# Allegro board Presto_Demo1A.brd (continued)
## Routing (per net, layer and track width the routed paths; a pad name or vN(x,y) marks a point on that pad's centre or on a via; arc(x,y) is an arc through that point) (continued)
A14: length 29.6
  TOP w0.2: U8.38 24.46,118.09 24.31,118.24 v2(24.3,118.24)
  INNER1 w0.2: v2(24.3,118.24) 23.16,117.11 23.05,117.11 22.7,116.75 22.7,115.44 20.4,113.15 20.4,111.14 18.67,109.4 14.75,109.4 14.45,109.1 14.45,100.2 14.08,99.83 J6.B10
A15: length 33
  TOP w0.2: U8.37 26.89,117.59 v2(26.9,117.6)
  INNER1 w0.2: J6.B9 10.88,97.3 13.75,97.3 14.85,98.4 14.85,108.8 15.05,109 18.83,109 20.8,110.97 20.8,112.98 25.42,117.6 v2(26.9,117.6)
A16: length 24.1
  TOP w0.2: J6.B24 12.24,135.39 12.9,136.05 12.9,137.88 16.52,141.51 20.71,141.51 21.95,140.26 21.95,139.94 21.95,139.93 21.95,138 23.55,136.4 23.55,134.86 23.54,134.85 23.54,134.35 24.03,133.86 24.83,133.86 24.84,133.86 U6.36
A17: length 25.4
  TOP w0.2: J6.B23 11.77,133.75 11.77,134.22 13.3,135.75 13.3,137.72 16.69,141.11 20.54,141.11 21.55,140.1 21.55,137.84 23.14,136.24 23.14,134.18 23.92,133.41 24.55,133.41 24.6,133.36 U6.35
A18: length 93.9
  TOP w0.2: U6.33 24.74,132.36 v2(24.3,132.8) 23.8,132.8 22.74,133.86 22.74,136.08 21.15,137.67 21.15,139.93 20.38,140.71 16.85,140.71 13.7,137.55 13.7,131.62 12.39,130.31 J6.B22 ; U7.6 17.78,81.53 18.1,81.85 v2(18.1,81.9)
  INNER2 w0.2: v2(18.1,81.9) 18.15,81.84 20.41,81.84 29.2,90.63 29.2,109.45 21.6,117.04 21.6,119.78 22.3,120.48 22.3,125.65 23.5,126.85 24.97,126.85 26.14,128.03 26.14,130.96 v2(24.3,132.8)
A19: length 94.3
  TOP w0.2: J6.B21 13.27,127.77 14.1,128.6 14.1,137.39 17.02,140.31 20.21,140.31 20.75,139.77 20.75,137.51 22.34,135.91 22.34,133.69 24.13,131.9 v2(24.3,131.9) 25.6,131.9 U6.32 ; v2(18,82.8) U7.5
  INNER2 w0.2: v2(24.3,131.9) 25.74,130.46 25.74,128.19 24.8,127.25 23.34,127.25 21.9,125.81 21.9,120.65 21.2,119.95 21.2,117.21 21.2,117.21 21.2,116.88 28.8,109.28 28.8,90.8 21.15,83.15 19.2,83.15 18.84,82.8 v2(18,82.8)
A20: length 80.6
  TOP w0.2: v2(24.05,130.95) 24.05,130.95 24.15,130.85 25.64,130.85 U6.30 ; U7.4 16.67,84.1 v2(18.74,84.1)
  INNER1 w0.2: J6.B20 10.87,126.57 10.02,127.42 10.02,128.12 11.54,129.65 14.6,129.65 16.1,131.15 17.5,131.15 18.15,130.5 23.59,130.5 v2(24.05,130.95)
  INNER2 w0.2: v2(24.05,130.95) 23.49,130.4 23.49,129.85 23.8,129.54 23.8,128.85 21.1,126.14 21.1,120.98 20.4,120.28 20.4,117.54 20.4,117.54 20.4,117.21 20.4,116.55 20.4,116.55 20.4,114.36 28,106.77 28,91.13 24.02,87.16 20.15,87.16 18.74,85.75 v2(18.74,84.1)
A21: length 79.9
  TOP w0.2: U6.29 25.64,130.35 24.35,130.35 v2(24.1,130.1) ; v2(20.4,86.55) 19.25,85.4 16.7,85.4 16.64,85.34
  INNER1 w0.2: J6.B19 11.77,123.59 11.77,127.11 12.26,127.61 13.1,127.61 14.75,129.25 14.77,129.25 16.22,130.7 17.38,130.7 17.98,130.1 v2(24.1,130.1)
  INNER2 w0.2: v2(24.1,130.1) 24.15,130.1 25.02,129.23 25.02,128.11 24.56,127.65 23.17,127.65 21.5,125.98 21.5,120.81 20.8,120.12 20.8,117.38 20.8,116.71 20.8,116.71 20.8,114.53 28.4,106.93 28.4,90.96 23.98,86.55 v2(20.4,86.55)
A22: length 83.3
  TOP w0.2: v2(23.2,129.1) 23.46,129.36 U6.27 ; U7.2 14.51,86.61 v2(14.5,86.6)
  INNER1 w0.2: v2(23.2,129.1) 22.6,129.7 18.2,129.7 17.9,129.4 17.01,129.4 17,129.41 16.5,129.41 16.14,129.05 16.14,129.05 15.6,128.5 14.73,128.5 13.64,127.42 13.64,126.56 13.24,126.16 13.24,125.28 13.25,125.28 13.25,124.78 14,124.03 14,120.82 13.33,120.15 J6.B18
  INNER2 w0.2: v2(23.2,129.1) 20.7,126.6 20.7,121.14 20,120.45 20,117.71 20,117.38 20,117.38 20,116.38 20,116.38 20,114.19 27.6,106.6 27.6,91.3 23.86,87.56 19.96,87.56 19,86.6 v2(14.5,86.6)
A23: length 27.2
  TOP w0.2: v2(26.95,128.9) 25.69,128.9 U6.26
  INNER1 w0.2: J6.B17 10.87,118.32 12.02,119.48 13.22,119.48 14.4,120.65 14.4,124.2 13.65,124.95 13.65,125.44 13.64,125.45 13.64,126 14.04,126.39 14.04,127.25 14.9,128.11 17.1,128.11 17.4,128.4 23.4,128.4 23.96,128.96 26.89,128.96 v2(26.95,128.9)
AEN/: length 12.6
  TOP w0.2: 16.64,80.26 16.56,80.19 11.39,80.19 10.58,81 10.25,81 9.15,82.1 4.92,82.1 J6.E3
BRD/: length 21.5
  TOP w0.2: U7.13 22.69,78.99 22.1,78.4 22.1,67.65 19.5,65.05 16.67,65.05 U48.7
BRESET: length 21.4
  TOP w0.2: U7.12 26,77.75 23.05,77.75 22.5,77.2 22.5,66.6 19.65,63.75 U48.8
BUF_OUT: length 1.4
  TOP w0.5: R50.1 C41.2
BWR/: length 21.3
  TOP w0.2: U48.6 18.94,66.29 21.7,69.05 21.7,79.4 22.6,80.3 25.99,80.3 26.04,80.26
CENTER-TAP: length 2
  TOP w0.5: R21.2 C41.1
CLKC: length 85.8
  TOP w0.102: 55.5,121.25 52.85,121.25 U1.C3
  TOP w0.2: 55.5,121.25 v2(56.05,121.25)
  INNER1 w0.2: v2(56.05,121.25) 64.8,121.25 66.74,119.31 66.74,119.2 67.1,118.84 67.21,118.84 69.8,116.25 82.25,116.25 83.2,115.3 83.2,105.15 80.8,102.75 80.8,71.3 v2(76.92,67.42)
  BOTTOM w0.2: R26.1 v2(76.92,67.42)
CLOCK+: length 59.1
  TOP w0.1: U2.J11 61.97,95.65 62.2,95.42 v1(62.2,95.3) ; U1.H4 51.6,126.7 v1(51.9,126.4)
  TOP w0.127: U50.31 67.92,83.75 68.35,83.75 68.43,83.67 69.27,83.67 69.75,84.15 69.75,85.57 v2(69.47,85.85)
  INNER1 w0.1: 55.59,119.36 55.56,119.36 55.55,119.37 55.27,119.37 54.97,119.67 54.97,121.73 55.3,122.06 55.3,123.93 55,124.23 55,125.23 53.64,126.59 52.09,126.59 v1(51.9,126.4) ; 67.77,94.03 67.75,94.05 67.75,94.07 67.47,94.35 64.18,94.35 63.25,95.27 62.5,95.27 62.48,95.3 v1(62.2,95.3) 62,95.53 61.9,95.53 59.79,95.53 59.02,96.31 59.02,104.63 59.01,104.64 59.01,104.67
  INNER1 w0.127: 59.01,104.67 59.01,112.01 56.45,114.57 56.45,119.03 56.12,119.36 55.59,119.36 ; 67.77,94.03 68.1,93.7 68.1,90.1 69.75,88.45 69.75,86.13 v2(69.47,85.85)
CLOCK-: length 60.3
  TOP w0.1: U1.H3 52.2,126.7 v1(51.9,127) ; v1(62.25,95.95) 62.25,95.8 62.4,95.65 U2.J12
  TOP w0.127: U50.30 67.94,83.35 68.35,83.35 68.42,83.42 69.38,83.42 70,84.04 70,85.57 v2(70.28,85.85)
  INNER1 w0.1: 59.26,104.67 59.26,104.64 59.25,104.63 59.25,96.4 59.89,95.76 61.92,95.76 62.02,95.75 v1(62.25,95.95) 62.25,95.85 62.6,95.5 63.35,95.5 64.27,94.58 67.56,94.58 67.91,94.23 67.93,94.23 67.94,94.22 ; v1(51.9,127) 51.9,126.95 52.04,126.81 53.74,126.81 55.22,125.33 55.22,124.33 55.53,124.02 55.53,121.97 55.2,121.64 55.2,119.76 55.36,119.6 55.58,119.6 55.59,119.61
  INNER1 w0.127: 67.94,94.22 68.35,93.81 68.35,90.21 70,88.56 70,86.13 v2(70.28,85.85) ; 59.26,104.67 59.26,112.11 56.7,114.68 56.7,119.14 56.22,119.61 55.59,119.61
CONF_SW0: length 40.5
  TOP w0.102: U1.T11 v1(43.9,135.2)
  TOP w0.2: v2(61.75,127.45) 61.75,127.65 62.5,128.4 62.5,132.85 64.15,134.5 66.51,134.5 SW1.1
  INNER1 w0.102: 55.59,128.6 44.96,128.6 43.34,130.22 43.34,134.64 v1(43.9,135.2)
  INNER1 w0.2: 55.59,128.6 55.63,128.6 55.88,128.35 59.5,128.35 60.39,127.45 61.2,127.45 61.2,127.45 v2(61.75,127.45)
  BOTTOM w0.2: RN1.1 62,127.2 v2(61.75,127.45)
CONF_SW1: length 34.7
  TOP w0.102: U1.R11 v1(43.9,134.2)
  TOP w0.2: 63.25,128.88 v2(63.25,128.9) 63.25,129.89 63.24,129.9 63.24,130.4 63.25,130.41 63.25,131.25 63.95,131.95 SW1.2
  INNER1 w0.102: 55.59,129.55 55.54,129.6 44.3,129.6 43.52,130.38 43.52,133.82 v1(43.9,134.2)
  INNER1 w0.2: v2(63.25,128.9) 63.25,128.88 63.11,128.74 61.23,128.74 60.42,129.55 55.59,129.55
  BOTTOM w0.2: v2(63.25,128.9) 63.67,128.48 63.67,128.33 64.4,127.6 RN1.2
CONF_SW2: length 24.2
  TOP w0.102: U1.N8 v1(47.9,132.2)
  TOP w0.2: v2(64.5,128.6) 64.54,128.64 64.54,129.1 64.85,129.41 SW1.3
  INNER1 w0.102: v1(47.9,132.2) 49.52,130.58 55.17,130.58 55.4,130.35 55.59,130.35
  INNER1 w0.2: 55.59,130.35 64.05,130.35 64.5,129.9 v2(64.5,128.6)
  BOTTOM w0.2: v2(64.5,128.6) 65.1,128 RN1.3
CONF_SW3: length 26.4
  TOP w0.102: U1.M9 v1(46.88,130.22)
  TOP w0.2: SW1.4 66.45,126.8 64.65,126.8 63.85,127.59 63.85,129.65 v2(63.85,129.65)
  INNER1 w0.102: v1(46.88,130.22) 47.3,129.8 55.44,129.8 55.59,129.95
  INNER1 w0.2: 63.85,129.65 v2(63.85,129.65) 63.1,129.65 62.59,129.14 61.4,129.14 60.59,129.95 55.59,129.95
  BOTTOM w0.2: v2(63.85,129.65) 64.7,129.65 65.95,128.4 RN1.4
D0: length 36.5
  TOP w0.2: U8.26 25.6,112.05 24.4,112.05 v2(24.3,111.95) ; v2(23.45,100.65) 23.52,100.58 U9.37
  INNER2 w0.2: v2(23.45,100.65) 21.9,99.1 18.4,99.1 17.8,98.5 15.1,98.5 14,97.4 12.35,97.4 11.15,96.2 10.95,96.2 9.5,94.75 J6.E8
  BOTTOM w0.2: v2(23.45,100.65) 23.45,101.24 24.7,102.5 24.7,111.55 v2(24.3,111.95)
D1: length 36.4
  TOP w0.2: U8.27 25.59,112.64 24.5,112.64 24.3,112.84 v2(24.3,112.9) ; U9.38 24.49,101.08 v2(24.32,101.25)
  INNER2 w0.2: J6.E9 9.34,97.29 10.8,98.75 11.4,98.75 11.9,99.25 14.1,99.25 14.35,99 16.99,99 18.45,100.45 22.39,100.45 23.2,101.25 23.7,101.25 23.71,101.25 24.31,101.25 v2(24.32,101.25)
  BOTTOM w0.2: v2(24.32,101.25) 25.15,102.09 25.15,112.05 v2(24.3,112.9)
D2: length 37.7
  TOP w0.2: U8.29 25.59,113.64 24.79,113.64 24.74,113.7 23.85,113.7 21.84,111.69 21.84,103.06 22.8,102.1 v2(23.45,102.1) 25.49,102.1 U9.40
  INNER2 w0.2: v2(23.45,102.1) 22.61,102.1 22.31,102.4 21.7,102.4 21.3,102.8 18.15,102.8 17.4,102.05 15.9,102.05 14.3,100.45 11.45,100.45 11.22,100.68 10.31,100.68 9.46,99.83 J6.E10
D3: length 46.4
  TOP w0.2: U8.30 24.91,114.09 24.9,114.1 23.68,114.1 21.45,111.86 21.45,102.81 22.2,102.05 v2(22.2,101.65) ; U9.41 26.67,102.58 v2(26.8,102.45)
  INNER1 w0.2: v2(26.8,102.45) 24.66,102.45 23.7,101.5 23.2,101.5 23.04,101.65 v2(22.2,101.65)
  INNER2 w0.2: J6.E11 9.66,102.37 11.64,104.35 13.25,104.35 14.13,103.47 16.23,103.47 16.44,103.68 18.23,103.68 18.9,104.35 20.33,104.35 21.88,102.8 23.49,102.8 23.6,102.69 24.21,102.69 24.5,102.4 26.75,102.4 v2(26.8,102.45)
D4: length 58.5
  TOP w0.2: U8.32 26.45,115.09 26.46,115.09 27.26,115.09 27.95,114.4 27.95,112.1 26.95,111.1 23.6,111.1 22.24,109.75 22.24,103.5 22.45,103.3 v2(23.85,103.3) 23.85,103.3 24.35,103.3 24.62,103.58 U9.43
  INNER2 w0.2: v2(23.85,103.3) 21.95,103.3 18.65,106.6 14.3,106.6 13.07,105.38 12.12,105.38 11.6,105.9 10.29,105.9 9.3,104.91 J6.E12
  BOTTOM w0.2: v2(23.85,88.65) 23.85,98.95 22.8,100 22.8,101.39 22.8,101.4 22.8,101.9 22.8,101.91 22.8,102.65 23.45,103.3 v2(23.85,103.3)
D5: length 42
  TOP w0.2: U9.44 v2(24.07,104.08) 24.05,104.05 22.99,104.05 22.64,104.4 22.64,109.58 23.77,110.7 27.12,110.7 28.35,111.93 28.35,114.65 27.51,115.49 26.62,115.49 26.52,115.59 U8.33
  INNER2 w0.2: J6.E13 9.37,107.45 9.57,107.25 9.57,107.25 10.22,106.6 11.45,106.6 12.3,107.45 19.2,107.45 22.55,104.1 24.05,104.1 v2(24.07,104.08)
D6: length 36.8
  TOP w0.2: U9.46 25.49,105.05 23.3,105.05 v2(23.25,105.1) ; U8.35 25.64,116.6 24.41,116.6 24.2,116.39 23.7,116.39 23.58,116.5 v2(23.3,116.5)
  INNER2 w0.2: J6.E14 9.41,109.99 10.3,109.1 11.7,109.1 11.91,109.31 19.03,109.31 v2(23.25,105.1)
  BOTTOM w0.2: v2(23.3,116.5) 23.25,116.45 v2(23.25,105.1)
D7: length 36.9
  TOP w0.2: U8.36 25.64,117.1 24.06,117.1 23.95,116.99 v2(23.95,116.99) ; v2(24.05,105.66) 24.1,105.6 25.49,105.6 U9.47
  INNER2 w0.2: v2(24.05,105.66) 19.4,110.3 12.35,110.3 11.5,111.15 10.5,111.15 9.12,112.53 J6.E15
  BOTTOM w0.2: v2(24.05,105.66) 23.7,106.01 23.7,115.9 23.95,116.15 v2(23.95,116.99)
D8: length 30.3
  TOP w0.2: J6.E24 4.87,140.92 6.56,142.62 14.23,142.62 15.53,143.91 21.7,143.91 22.36,143.25 22.38,143.25 24.35,141.28 24.35,141.26 24.35,141.26 24.35,139.81 24.8,139.36 U6.47
D9: length 32.6
  TOP w0.2: U6.46 24.8,138.86 24.75,138.91 24.68,138.91 23.95,139.64 23.95,141.09 23.95,141.1 23.95,141.11 22.21,142.86 22.19,142.86 21.54,143.51 15.69,143.51 14.4,142.22 6.76,142.22 5.45,140.9 5.45,136.6 5.72,136.33 5.72,134.73 4.87,133.88 J6.E23
D10: length 34.1
  TOP w0.2: J6.E22 5.72,131.16 5.72,134.05 5.77,134.1 5.77,134.22 7.07,135.52 7.07,137.42 7.45,137.8 7.45,141.05 8.21,141.81 14.57,141.81 15.86,143.11 21.37,143.11 22.02,142.45 22.04,142.45 23.55,140.95 23.55,140.93 23.55,140.93 23.55,139.11 24.8,137.86 U6.44
D11: length 35.6
  TOP w0.2: U6.43 24.7,137.36 23.15,138.91 23.15,139.44 23.15,139.44 23.15,140.76 23.15,140.76 23.15,140.78 21.88,142.06 21.86,142.06 21.21,142.71 16.02,142.71 11.37,138.06 8.43,138.06 7.47,137.09 7.47,128.12 7,127.65 4.99,127.65 J6.E21
D12: length 38.1
  TOP w0.2: U6.41 24.73,136.36 22.75,138.34 22.75,139.6 22.75,139.6 22.75,140.6 22.75,140.6 22.75,140.62 21.71,141.66 21.69,141.66 21.04,142.31 16.19,142.31 11.54,137.66 8.6,137.66 7.87,136.92 7.87,125.95 7.15,125.23 J6.E20
D13: length 40.3
  TOP w0.2: J6.E19 5.01,122.55 7.05,122.55 8.27,123.77 8.27,136.76 8.76,137.25 11.7,137.25 16.36,141.91 20.88,141.91 22.35,140.43 22.35,139.77 22.35,139.77 22.35,138.17 24.66,135.86 U6.40
D+: length 78.1
  TOP w0.102: v1(61.27,91.17) U2.N11
  INNER1 w0.127: v2(115.25,113.19) 114.97,113.47 114.48,113.47 114.3,113.29 114.3,107.88 114.45,107.72 114.45,107.33 v2(114.73,107.05)
  BOTTOM w0.102: v1(61.27,91.17) 61.3,91.17 61.72,90.75 62.33,90.75 62.75,90.32 67.25,90.32 67.27,90.31 67.91,90.31 67.92,90.3 67.94,90.3
  BOTTOM w0.127: R2000.2 115.91,113.19 v2(115.25,113.19) 114.47,113.19 C2001.1 ; 67.94,90.3 79.17,90.3 84.9,96.02 84.9,96.23 84.9,96.23 84.9,96.34 84.9,96.34 84.9,106.44 85.07,106.62 112.54,106.62 112.89,106.26 114.18,106.26 114.45,106.54 114.45,106.77 v2(114.73,107.05)
D-: length 77
  TOP w0.102: U2.P11 61.75,90.65 61.85,90.75 v1(62.25,91.15)
  INNER1 w0.127: v2(113.92,107.05) 114.2,107.33 114.2,107.62 114.05,107.77 114.05,113.4 114.37,113.72 114.97,113.72 v2(115.25,114)
  BOTTOM w0.102: v1(62.25,91.15) 62.85,90.55 67.94,90.55
  BOTTOM w0.127: 67.94,90.55 79.07,90.55 84.64,96.12 84.64,96.44 84.65,96.45 84.65,106.55 84.97,106.87 112.65,106.87 113,106.52 114.07,106.52 114.2,106.65 114.2,106.77 v2(113.92,107.05) ; R2001.2 115.84,114 v2(115.25,114) 114.54,114 C2000.1
DATA0+: length 27.3
  TOP w0.102: U2.B5 v1(55.25,103.15) ; U1.B6 v1(49.9,120.2)
  INNER1 w0.102: v1(55.25,103.15) 55.25,103.61 54.85,104.01 54.85,104.67 ; v1(49.9,120.2) 49.9,119.75 49.48,119.33 49.48,118.74
  INNER1 w0.127: 54.85,104.67 54.85,109.71 54.19,110.38 52.47,110.38 51.4,111.45 51.4,112.72 52,112.72 52,112.97 51.3,112.97 51.3,113.81 52,113.81 52,114.21 51.4,114.21 51.4,115.04 52,115.04 52,115.37 51.4,115.37 51.4,116.21 52,116.21 52,116.53 51.4,116.53 51.4,117.34 50.49,118.25 49.97,118.25 49.48,118.74
DATA0-: length 24.9
  TOP w0.102: U1.A6 v1(49.9,119.2) ; U2.A5 v1(55.25,104.15)
  INNER1 w0.102: v1(49.9,119.2) 49.9,118.78 49.95,118.74 ; v1(55.25,104.15) 55.08,104.32 55.08,104.56 55.09,104.57 55.09,104.64 55.1,104.66 55.1,104.67
  INNER1 w0.127: 49.95,118.74 50.19,118.5 50.6,118.5 51.65,117.45 51.65,116.79 52.25,116.79 52.25,115.95 51.65,115.95 51.65,115.62 52.25,115.62 52.25,114.79 51.65,114.79 51.65,114.46 52.25,114.46 52.25,113.56 51.55,113.56 51.55,113.23 52.25,113.23 52.25,112.47 51.65,112.47 51.65,111.56 52.58,110.63 54.29,110.63 55.1,109.82 55.1,104.67
DATA1+: length 27.2
  TOP w0.102: U1.D6 v1(49.9,122.2) ; U2.D5 v1(55.25,101.15)
  INNER1 w0.102: v1(55.25,101.15) 55.25,101.61 54.87,101.99 54.87,102.21 54.64,102.44 54.64,103.3 54.3,103.64 54.3,104.53 54.27,104.56 54.27,104.67 ; v1(49.9,122.2) 49.9,121.8 49.28,121.18 49.28,119.9 48.9,119.52 48.9,118.74
  INNER1 w0.127: 54.27,104.67 54.27,109.47 53.94,109.8 51.74,109.8 50.25,111.29 50.25,117.52 50.12,117.65 49.5,117.65 49.06,118.09 49.06,118.13 48.9,118.3 48.9,118.74
DATA1-: length 24.9
  TOP w0.102: U1.C6 v1(49.9,121.2) ; U2.C5 v1(55.25,102.15)
  INNER1 w0.102: v1(55.25,102.15) 54.87,102.53 54.87,103.39 54.53,103.73 54.53,104.66 54.52,104.67 ; v1(49.9,121.2) 49.51,120.81 49.51,119.81 49.15,119.45 49.15,118.74
  INNER1 w0.127: 54.52,104.67 54.52,109.58 54.05,110.05 51.85,110.05 50.5,111.4 50.5,117.62 50.22,117.9 49.61,117.9 49.32,118.19 49.32,118.24 49.15,118.4 49.15,118.74
DATA1.CLKA: length 156.1
  TOP w0.102: U1.K5 v1(50.9,129.2)
  TOP w0.2: 84.57,61.51 84.57,76.33 83.91,76.99 82.73,76.99 v2(82.73,77.92) ; 84.57,61.51 85.3,60.78 85.3,50.15 84.25,49.1 81.15,49.1 80.17,50.08 U38.11 ; 84.57,61.51 82.73,61.51
  INNER1 w0.102: 55.59,129 55.42,129 55.24,128.82 53.06,128.82 53.06,128.82 51.74,128.82 51.74,128.82 51.28,128.82 v1(50.9,129.2)
  INNER1 w0.2: 55.59,129 59.8,129 60.74,128.06 62.09,128.06 62.9,127.25 62.95,127.2 63.45,127.2 63.5,127.25 69.75,127.25 71.7,125.3 71.7,124.74 75.54,120.9 97.53,120.9 102.25,116.18 102.25,106.42 101.3,105.47 101.3,96.2 103.66,93.85 103.66,84.9 104.25,84.3 104.25,81.61 101.8,79.15 90.25,79.15 89.02,77.92 v2(82.73,77.92)
DATA1.VD0: length 86.6
  TOP w0.102: U1.M2 v1(53.9,131.2)
  INNER1 w0.102: 55.59,131.7 54.4,131.7 v1(53.9,131.2)
  INNER1 w0.2: 55.59,131.7 55.75,131.7 55.9,131.55 70.97,131.55 72.9,129.62 72.9,125.24 76.04,122.1 98.09,122.1 103.45,116.74 103.45,98.9 102.9,98.34 102.9,96.35 105.2,94.04 v2(105.2,92.6)
  BOTTOM w0.2: RN3.1 104.25,91.44 104.25,92.4 104.45,92.6 v2(105.2,92.6)
DATA1.VD1: length 85.6
  TOP w0.102: U1.M1 v1(54.9,131.2)
  INNER1 w0.102: v1(54.9,131.2) 54.95,131.15 55.59,131.15
  INNER1 w0.2: v2(105.4,91.6) 105.24,91.76 105.16,91.76 104.59,92.32 104.59,94.04 102.1,96.53 102.1,105.12 103.05,106.07 103.05,116.52 97.87,121.7 75.87,121.7 72.5,125.07 72.5,129.45 70.8,131.15 55.59,131.15
  BOTTOM w0.2: RN3.2 104.8,91 v2(105.4,91.6)
DATA1.VD2: length 89.3
  TOP w0.102: U1.N3 v1(52.9,132.2)
  INNER1 w0.102: v1(52.9,132.2) 53.35,131.75 53.35,131 53.55,130.8 55.54,130.8 55.59,130.75
  INNER1 w0.2: 55.59,130.75 70.63,130.75 72.1,129.28 72.1,124.9 75.7,121.3 97.7,121.3 102.65,116.35 102.65,106.25 101.7,105.3 101.7,96.37 104.19,93.87 104.19,91.96 104.79,91.36 104.79,91.35 105.15,91 105.16,91 105.35,90.81 v2(105.69,90.81)
  BOTTOM w0.2: RN3.3 105.48,90.6 v2(105.69,90.81)
DATA1.VD3: length 89.6
  TOP w0.102: U1.N1 v1(54.9,132.2)
  INNER1 w0.102: v1(54.9,132.2) 55.59,132.2
  INNER1 w0.2: 55.59,132.2 55.92,132.2 56.17,131.95 71.13,131.95 73.3,129.78 73.3,125.4 76.2,122.5 98.25,122.5 103.85,116.9 103.85,98.9 105.85,96.9 105.85,92.22 106.85,91.22 106.85,90.2 106.25,89.6 v2(105.1,89.6)
  BOTTOM w0.2: RN3.4 104.5,90.2 v2(105.1,89.6)
DATA1.VD4: length 93.9
  TOP w0.102: U1.P2 v1(53.9,133.2)
  INNER1 w0.102: v1(53.9,133.2) 54.35,132.75 55.55,132.75 55.59,132.71
  INNER1 w0.2: v2(105.28,86.73) 105.28,86.98 107.25,88.95 107.25,91.38 106.25,92.38 106.25,97.07 104.25,99.07 104.25,117.07 98.42,122.9 76.37,122.9 73.7,125.57 73.7,129.95 71.3,132.35 56.33,132.35 55.97,132.71 55.59,132.71
  BOTTOM w0.2: RN2.1 104.46,86.32 104.84,86.7 105.25,86.7 v2(105.28,86.73)
DATA1.VD5: length 94.4
  TOP w0.102: U1.P1 v1(54.9,133.2)
  INNER1 w0.102: v1(54.9,133.2) 55.59,133.2
  INNER1 w0.2: 55.59,133.2 56.05,133.2 56.5,132.75 71.5,132.75 74.1,130.15 74.1,125.73 76.53,123.3 98.58,123.3 104.65,117.23 104.65,99.23 106.65,97.23 106.65,92.6 107.65,91.6 107.65,88.78 106,87.14 v2(106,86.33)
  BOTTOM w0.15: RN2.2 104.72,85.92 104.8,86 105.67,86 v2(106,86.33)
DATA1.VD6: length 98.9
  TOP w0.102: U1.R2 v1(53.9,134.2)
  INNER1 w0.2: v2(107.32,86) 108.45,87.13 108.45,91.97 107.5,92.92 107.5,97.55 105.45,99.6 105.45,117.6 98.95,124.1 76.9,124.1 74.9,126.1 74.9,130.55 72.5,132.95 v2(72.5,133.55)
  INNER2 w0.1: 55.59,133.41 55.3,133.7 54.4,133.7 v1(53.9,134.2)
  INNER2 w0.2: v2(72.5,133.55) 72.15,133.2 55.8,133.2 55.59,133.41
  BOTTOM w0.2: v2(107.32,86) 106.94,85.62 104.96,85.62 104.85,85.52 RN2.3
DATA1.VD7: length 96.6
  TOP w0.102: U1.R1 v1(54.9,134.2)
  INNER1 w0.102: v1(54.9,134.2) 55.59,134.2
  INNER1 w0.2: v2(105.3,85) 105.83,85 106.72,85.88 106.72,87.27 108.05,88.6 108.05,91.8 107.05,92.8 107.05,97.4 105.05,99.4 105.05,117.4 98.75,123.7 76.7,123.7 74.5,125.9 74.5,130.35 71.7,133.15 56.75,133.15 55.7,134.2 55.59,134.2
  BOTTOM w0.2: v2(105.3,85) 105.18,85.12 RN2.4
DATA1.WSTAT_L: length 99.2
  TOP w0.102: U1.J6 v1(49.9,128.2)
  TOP w0.2: U22.11 103.28,82.39 v2(103.25,82.35)
  INNER1 w0.102: v1(49.9,128.2) 50.55,127.55 55.59,127.55
  INNER1 w0.2: 55.59,127.55 59.15,127.55 60.25,126.45 62.57,126.45 62.62,126.4 63.78,126.4 63.83,126.45 69.42,126.45 70.9,124.97 70.9,124.41 75.21,120.1 97.2,120.1 101.41,115.9 101.41,106.91 100.5,106 100.5,95.75 101.83,94.42 102.19,94.07 102.19,94.06 102.85,93.4 102.85,82.75 v2(103.25,82.35)
DATA2+: length 27.3
  TOP w0.102: U1.B5 v1(50.9,120.2) ; U2.D6 v1(56.25,101.15)
  INNER1 w0.102: 55.62,104.67 55.62,104.56 55.64,104.55 55.64,102.06 56.25,101.45 v1(56.25,101.15)
  INNER1 w0.127: 55.62,104.67 55.62,107.68 55.43,107.87 55.43,110.05 54.23,111.25 53.15,111.25 52.6,111.8 52.6,113.06 53.15,113.06 53.15,113.39 52.6,113.39 52.6,114.22 53.15,114.22 53.15,114.55 52.6,114.55 52.6,115.38 53.15,115.38 53.15,115.71 52.6,115.71 52.6,117.44 51.23,118.81 50.69,118.81 50.45,119.05 50.45,119.3 50.51,119.36 50.51,119.36 50.74,119.59 50.74,119.59 50.9,119.75 v1(50.9,120.2)
DATA2-: length 24.8
  TOP w0.102: U2.C6 v1(56.25,102.15) ; U1.A5 v1(50.9,119.2)
  INNER1 w0.102: 55.88,104.67 55.87,104.66 55.87,102.54 56.25,102.16 v1(56.25,102.15)
  INNER1 w0.127: v1(50.9,119.2) 51.2,119.2 52.85,117.55 52.85,115.97 53.4,115.97 53.4,115.13 52.85,115.13 52.85,114.8 53.4,114.8 53.4,113.97 52.85,113.97 52.85,113.64 53.4,113.64 53.4,112.81 52.85,112.81 52.85,111.91 53.26,111.5 54.34,111.5 55.69,110.16 55.69,108.02 55.88,107.82 55.88,104.67
DATA3+: length 1.4
  TOP w0.102: U1.D5 v1(50.9,122.2) ; U2.B6 v1(56.25,103.15)
DATA3-: length 1.4
  TOP w0.102: U2.A6 v1(56.25,104.15) ; U1.C5 v1(50.9,121.2)
DATA.BA0: length 66
  TOP w0.102: U1.H16 v1(38.9,126.2)
  TOP w0.2: U6.13 18.98,133.86 20.95,131.88 v2(20.95,131.35) ; U8.2 18.84,122.59 19.1,122.85 19.1,123.7 18.8,124 v2(18,124) ; v2(16.6,100.1) 17.89,100.1 U9.13
  INNER1 w0.102: v1(38.9,126.2) 38.32,126.2
  INNER1 w0.2: v2(18,124) 18,125.15 18.84,126 38.11,126 38.32,126.2
  INNER2 w0.2: v2(20.95,131.35) 19.35,131.35 18,130 v2(18,124)
  BOTTOM w0.2: v2(16.6,100.1) 17.3,100.8 17.3,106 18,106.7 v2(18,124)
DATA.BA1: length 63.9
  TOP w0.102: U1.H15 v1(39.9,126.2)
  TOP w0.2: U9.14 19.02,99.58 19.25,99.8 v2(19.35,99.8) ; U8.3 19.04,122.09 v2(20.05,123.1) 20.05,124.83 20.3,125.09 20.3,131.96 18.91,133.36 U6.14
  INNER1 w0.102: v1(39.9,126.2) 39.44,126.2 39.06,125.82 38.5,125.82 38.32,125.63
  INNER1 w0.2: 38.32,125.63 38.28,125.59 20.79,125.59 20.1,124.9 20.1,123.15 v2(20.05,123.1)
  BOTTOM w0.2: v2(19.35,99.8) 20.45,99.8 21.25,100.6 21.25,121.9 v2(20.05,123.1)
DATA.BA2: length 66.4
  TOP w0.102: U1.G14 v1(40.9,125.2)
  TOP w0.2: U6.16 18,132.4 17.01,132.4 17,132.41 16.3,132.41 16.1,132.2 16.1,121.45 16.56,120.99 17.06,120.99 17.17,121.09 U8.5 19.04,121.09 19.29,121.35 v2(20.05,121.35) ; v2(20.6,101.6) 20.05,101.05 20.05,99.5 19.4,98.85 19,98.85 18.72,98.58 U9.16
  INNER1 w0.102: 38.32,124.8 40.03,124.8 40.44,125.2 v1(40.9,125.2)
  INNER1 w0.2: v2(20.05,121.35) 21.05,122.36 21.05,124.29 21.56,124.8 38.32,124.8
  BOTTOM w0.2: v2(20.6,101.6) 20.85,101.85 20.85,120.55 v2(20.05,121.35)
DATA.BA3: length 63.1
  TOP w0.102: U1.G16 v1(38.9,125.2)
  TOP w0.2: v2(19.2,98.05) 17.94,98.05 U9.17 ; v2(19.4,120.6) 18.05,120.6 U8.6 ; U6.17 18.89,131.86 19.9,130.84 19.9,125.26 v2(19.4,124.75)
  INNER1 w0.102: 38.32,125.2 38.44,125.2 38.45,125.2 v1(38.9,125.2)
  INNER1 w0.2: v2(19.4,120.6) 19.45,120.64 19.45,121.6 19.8,121.95 19.8,121.95 20.65,122.81 20.65,123.35 20.65,123.36 20.65,124.45 21.39,125.2 38.32,125.2
  BOTTOM w0.2: v2(19.2,98.05) 18.74,98.5 18.74,100.05 19.1,100.41 19.35,100.41 19.99,101.05 19.99,101.9 20.45,102.35 20.45,119.6 19.45,120.6 v2(19.4,120.6) v2(19.4,124.75)
DATA.BD0: length 33.6
  TOP w0.102: U1.F16 v1(38.9,124.2)
  TOP w0.2: U9.2 v2(16.57,105.58)
  INNER1 w0.102: 38.32,123.95 38.65,123.95 v1(38.9,124.2)
  INNER1 w0.2: v2(16.57,105.58) 18.2,105.58 18.71,106.08 19.27,106.08 22.69,109.5 25.14,109.5 34,118.36 34,120.95 37,123.95 38.32,123.95
DATA.BD1: length 33
  TOP w0.102: U1.F15 v1(39.9,124.2)
  TOP w0.2: U9.3 v2(19.12,105.08)
  INNER1 w0.102: v1(39.9,124.2) 39.4,123.7 39.4,123.05 39.15,122.8 38.42,122.8 38.32,122.7
  INNER1 w0.2: v2(19.12,105.08) 20.21,105.08 20.5,105.37 20.5,106.18 23.02,108.7 25.47,108.7 34.8,118.03 34.8,120.58 36.92,122.7 38.32,122.7
DATA.BD2: length 35.3
  TOP w0.102: U1.E16 v1(38.9,123.2)
  TOP w0.2: U9.5 17.04,104.08 16.94,103.97 16.44,103.97 16.33,104.08 v2(15.97,104.08)
  INNER1 w0.1: 38.32,123.2 v1(38.9,123.2)
  INNER1 w0.2: v2(15.97,104.08) 16.16,104.26 16.44,103.97 16.94,103.97 17.73,104.77 17.78,104.77 18.18,105.18 18.37,105.18 18.87,105.68 19.32,105.68 19.32,105.68 19.43,105.68 22.85,109.1 25.3,109.1 34.4,118.2 34.4,120.75 36.75,123.1 36.97,123.1 37.07,123.2 38.32,123.2
DATA.BD3: length 33.3
  TOP w0.102: U1.E15 v1(39.9,123.2)
  TOP w0.2: v2(19.15,103.7) 19.02,103.58 U9.6
  INNER1 w0.102: 38.32,122.3 38.46,122.3 38.74,122.58 39.28,122.58 v1(39.9,123.2)
  INNER1 w0.2: v2(19.15,103.7) 20.25,103.7 20.9,104.35 20.9,106.01 23.19,108.3 25.64,108.3 35.2,117.86 35.2,120.42 37.08,122.3 38.32,122.3
DATA.BD4: length 40.7
  TOP w0.102: U1.E13 v1(41.9,123.2)
  TOP w0.2: v2(15.95,102.7) 16.18,102.47 16.94,102.47 17.04,102.58 U9.8
  INNER1 w0.102: 38.32,121.9 38.4,121.82 39.06,121.82 39.28,122.04 39.28,122.32 39.66,122.7 40.25,122.7 40.35,122.8 40.35,123.19 40.74,123.58 41.52,123.58 v1(41.9,123.2)
  INNER1 w0.2: v2(15.95,102.7) 16.18,102.47 18.05,102.47 18.66,103.08 20.28,103.08 21.3,104.1 21.3,105.85 23.35,107.9 25.8,107.9 35.6,117.7 35.6,120.25 37.25,121.9 38.32,121.9
DATA.BD5: length 37.5
  TOP w0.102: U1.E12 v1(42.9,123.2)
  TOP w0.2: U9.9 v2(19.07,102.08)
  INNER1 w0.102: v1(42.9,123.2) 42.28,122.58 41.74,122.58 41.52,122.36 41.52,121.87 41.23,121.58 40.74,121.58 40.52,121.36 40.52,120.87 40.23,120.58 39.74,120.58 39.52,120.36 39.52,120.28 39.06,119.82 38.38,119.82 38.32,119.75
  INNER1 w0.2: 38.32,119.75 37.07,119.75 36.4,119.08 36.4,117.37 26.13,107.1 23.68,107.1 22.1,105.52 22.1,103.13 21.25,102.28 19.28,102.28 v2(19.07,102.08)
DATA.BD6: length 33.6
  TOP w0.102: U1.B15 v1(39.9,120.2)
  TOP w0.2: U9.11 v2(19.07,101.08)
  INNER1 w0.102: 39.45,119.76 39.53,119.84 39.55,119.84 v1(39.9,120.2)
  INNER1 w0.2: 39.45,119.76 39.45,119.14 39.08,118.77 37,118.77 36.8,118.57 36.8,117.2 26.3,106.7 23.85,106.7 22.64,105.5 22.64,103 21.55,101.9 21.55,101.4 21.1,100.95 20.25,100.95 20.12,101.08 v2(19.07,101.08)
DATA.BD7: length 36
  TOP w0.102: U1.B16 v1(38.9,120.2)
  TOP w0.2: U9.12 16.97,100.58 16.8,100.75 v2(16.05,100.75)
  INNER1 w0.102: 38.35,120.15 38.4,120.2 v1(38.9,120.2)
  INNER1 w0.2: v2(16.05,100.75) 16.89,100.75 18.82,102.68 21.08,102.68 21.7,103.3 21.7,105.68 23.52,107.5 25.97,107.5 36,117.53 36,119.25 36.9,120.15 38.35,120.15
DATA.BD8: length 64.6
  TOP w0.102: U1.F12 v1(42.9,124.2)
  TOP w0.2: U8.23 15.46,112.09 13.85,113.7 13.85,113.78 13.8,113.83 13.8,125.25 v2(14.25,125.7) 14.04,125.91 14.04,127.2 14.5,127.66 14.5,137.15 16.7,139.35 18.04,139.35 U6.2
  INNER1 w0.102: v1(42.9,124.2) 42.9,124.74 40.64,127 38.32,127
  INNER1 w0.2: 38.32,127 17.99,127 16.69,125.7 v2(14.25,125.7)
DATA.BD9: length 62.9
  TOP w0.102: U1.G11 v1(43.9,125.2)
  TOP w0.2: U8.22 15.61,112.59 14.2,114 14.2,124.45 14.44,124.7 14.44,124.7 14.9,125.16 14.9,126.7 v2(14.65,126.95) 14.9,127.2 14.9,136.86 16.14,138.1 16.15,138.1 16.9,138.85 18.04,138.85 U6.3
  INNER1 w0.102: v1(43.9,125.2) 42.7,125.2 40.5,127.4 38.32,127.4
  INNER1 w0.2: 38.32,127.4 17.82,127.4 17.32,126.89 14.7,126.89 v2(14.65,126.95)
DATA.BD12: length 56.3
  TOP w0.102: U1.F13 v1(41.9,124.2)
  TOP w0.2: U8.17 17.24,115.09 17.23,115.09 15.76,115.09 14.65,116.2 14.65,124.05 v2(15.05,124.45) 15.3,124.7 15.3,135.06 16.6,136.36 U6.8
  INNER1 w0.102: 38.32,126.6 38.47,126.75 40.22,126.75 41.52,125.45 41.52,125.04 41.9,124.66 v1(41.9,124.2)
  INNER1 w0.2: 38.32,126.6 18.15,126.6 16,124.45 v2(15.05,124.45)
DATA.BD13: length 55.4
  TOP w0.102: U1.F14 v1(40.9,124.2)
  TOP w0.2: U8.16 17.17,115.59 17.06,115.49 16.01,115.49 15.45,116.05 v2(15.45,118.25) 15.45,119.4 15.7,119.65 15.7,134.86 16.7,135.86 U6.9
  INNER1 w0.102: v1(40.9,124.2) 40.44,124.2 40.06,124.58 38.67,124.58 38.48,124.39 38.32,124.39
  INNER1 w0.2: 38.32,124.39 22.04,124.39 21.49,123.84 21.49,121.85 19.9,120.26 19.9,119.37 19.9,119.36 19.9,119.34 19.54,118.99 19.52,118.99 18.48,117.95 15.75,117.95 v2(15.45,118.25)
DATA.BD14: length 45
  TOP w0.102: U1.C15 v1(39.9,121.2)
  TOP w0.2: U6.11 19.14,134.86 21.95,132.05 21.95,120.7 23,119.65 23,118.55 v2(22.45,118) 21.04,116.59 U8.14
  INNER2 w0.102: v1(39.9,121.2) 39.44,121.2 38.99,120.75 38.7,120.75
  INNER2 w0.2: 38.7,120.75 38.5,120.95 38.5,121 38.15,121.35 27.34,121.35 25.74,119.75 23.8,119.75 23.1,119.05 23.1,118.65 v2(22.45,118)
DATA.BD15: length 41.6
  TOP w0.102: U1.C16 v1(38.9,121.2)
  TOP w0.2: U8.13 20.49,117.09 v2(22.25,118.85) 22.25,119.7 21.55,120.4 21.55,131.84 19.04,134.36 U6.12
  INNER2 w0.2: v1(38.9,121.2) 38.35,121.75 27.51,121.75 27.51,121.75 27.18,121.75 25.57,120.15 23.55,120.15 v2(22.25,118.85)
DATA.CLKB: length 41.5
  TOP w0.1: 38.32,127.7 U1.J16
  TOP w0.2: 38.32,127.7 37.75,127.7 v2(33.75,123.7)
  INNER1 w0.2: v2(33.75,123.7) 33.5,123.95 22.4,123.95 21.89,123.44 21.89,121.68 20.3,120.09 20.3,119.2 20.3,119.2 20.3,119.18 19.71,118.59 19.69,118.59 18.6,117.5 12.1,117.5 10.52,115.92 10.51,115.92 10.02,115.42 10.02,115.42 9.67,115.07 J6.E16
DDIR: length 63.7
  TOP w0.2: U7.1 v2(18.02,87.88) ; U8.24 18.09,111.55 v2(19.25,111.55) 19.25,106.45 18.88,106.08 U9.1 ; v2(19.4,139.55) 19.1,139.85 18.78,139.85 18.78,139.86 U6.1
  BOTTOM w0.2: v2(18.02,87.88) 17.7,88.2 17.7,105.7 19.25,107.25 v2(19.25,111.55) 18.65,112.15 18.65,112.43 18.65,112.43 18.65,138.81 v2(19.4,139.55)
DDR_A0: length 37.7
  TOP w0.102: U13.M8 v1(34.3,89.5) ; U2.C1 50.9,102.5 44.65,102.5 43.1,100.95 34.8,100.95 33.85,101.9 33.85,102.85 v1(34.3,103.3) U12.M8
  INNER2 w0.102: v1(34.3,103.3) 34.1,103.1 34.1,102.97 33.5,102.37 33.5,96.85 34.85,95.5 35.24,95.5 35.48,95.26 35.48,91.13 35,90.65 35,90.2 v1(34.3,89.5)
DDR_A1: length 38.3
  TOP w0.102: U12.M3 v1(34.3,108.1) ; U2.D1 v1(51.25,101.15) ; U13.M3 v1(34.3,94.3)
  INNER1 w0.102: v1(34.3,108.1) 33.88,107.68 33.88,94.72 v1(34.3,94.3)
  INNER2 w0.102: v1(51.25,101.15) 38.75,101.15 37.9,102 37.9,104.85 37.25,105.5 35.55,105.5 34.3,106.75 v1(34.3,108.1)
DDR_A2: length 35.8
  TOP w0.102: U13.M7 34.3,91.1 v1(34.3,91.6) ; v1(34.3,104.1) U12.M7 35.2,105 v1(36.7,105) ; U2.E1 v1(51.25,100.15)
  INNER2 w0.102: v1(36.7,105) 37,105 37.72,104.28 37.72,101.92 38.67,100.97 50.43,100.97 v1(51.25,100.15) ; v1(34.3,91.6) 33.92,91.98 33.92,96.13 33.3,96.75 33.3,102.43 33.92,103.05 33.92,103.46 34.3,103.84 v1(34.3,104.1)
DDR_A3: length 39.3
  TOP w0.102: U12.N2 v1(33.5,108.9) ; U13.N2 v1(33.5,95.1) 33.1,95.5 33.1,96.4 33.8,97.1 51.75,97.1 52.11,97.46 52.11,97.9 51.75,98.25 U2.F1
  BOTTOM w0.102: v1(33.5,108.9) 33.88,108.52 33.88,107.97 34.75,107.1 34.75,105.05 34.5,104.8 33.5,104.8 33.1,104.4 33.1,103.16 33.34,102.92 33.34,96.54 33.1,96.3 33.1,95.5 v1(33.5,95.1)
DDR_A4: length 36.8
  TOP w0.102: U2.G1 50.5,97.65 50,98.15 44.95,98.15 42.4,100.7 34.45,100.7 33.5,101.65 v1(33.5,103.3) U12.N8 ; U13.N8 v1(33.5,89.5)
  BOTTOM w0.102: v1(33.5,89.5) 33.5,91.7 33.9,92.1 33.9,102.9 v1(33.5,103.3)
DDR_A5: length 34.5
  TOP w0.102: U2.H1 51.05,96.65 49.6,95.2 46.65,95.2 44.99,93.54 34.26,93.54 U13.N3 v1(33.5,94.3) ; U12.N3 v1(33.5,108.1)
  INNER1 w0.102: v1(33.5,108.1) 33.12,107.72 33.12,94.68 v1(33.5,94.3)
DDR_A6: length 34.8
  TOP w0.102: U12.N7 v1(33.5,104.1) ; U2.J1 50.7,95.65 50.05,95 50.05,93.75 49.6,93.3 46.15,93.3 45.5,92.65 33.9,92.65 v1(33.5,92.25) 33.5,91.1 U13.N7
  INNER2 w0.102: v1(33.5,104.1) 33.5,103.84 33.12,103.46 33.12,94.14 33.5,93.76 v1(33.5,92.25)
DDR_A7: length 44.5
  TOP w0.102: U2.K1 v1(51.25,94.15) ; U13.P2 v1(32.7,95.1) ; U12.P2 v1(32.7,108.9)
  INNER2 w0.1: 37.5,101.8 38.55,100.75 50.1,100.75 51.45,99.4 51.45,96.65 51.25,96.45 v1(51.25,94.15)
  INNER2 w0.102: 37.5,101.8 37.5,104.15 37.1,104.55 35.4,104.55 v1(34.3,105.65)
  BOTTOM w0.102: v1(32.7,95.1) 32.7,96 32.25,96.45 32.25,104.45 32.8,105 34.1,105 34.3,105.2 v1(34.3,105.65) 34.3,106.4 33.08,107.62 33.08,108.52 v1(32.7,108.9)
DDR_A8: length 37.1
  TOP w0.102: v1(32.7,89.5) U13.P8 33.5,90.3 34.85,90.3 35.1,90.55 35.1,91.3 34.7,91.7 34.7,92.15 34.95,92.4 49.65,92.4 50.9,93.65 U2.L1 ; U12.P8 v1(32.7,103.3)
  BOTTOM w0.102: v1(32.7,103.3) 33.1,102.9 33.1,96.56 32.92,96.38 32.92,95.42 33.1,95.24 33.1,89.85 32.75,89.5 v1(32.7,89.5)
DDR_A9: length 34.9
  TOP w0.102: U12.P3 v1(32.7,108.1) ; v1(32.7,94.3) U13.P3 33.85,93.15 39.05,93.15 39.15,93.05 v1(44.55,93.05) ; U2.M1 v1(51.25,92.15)
  INNER1 w0.102: v1(32.7,108.1) 32.32,107.72 32.32,94.68 v1(32.7,94.3)
  INNER2 w0.102: v1(51.25,92.15) 51.15,92.25 45.3,92.25 44.55,93 v1(44.55,93.05)
DDR_A10: length 36.7
  TOP w0.102: v1(35.1,91.95) 44.85,91.95 46.33,90.47 50.52,90.47 51.7,91.65 U2.N1 ; U12.M2 v1(34.3,108.9) ; U13.M2 v1(34.3,95.1)
  INNER1 w0.102: v1(34.3,95.1) 34.3,94.84 34.68,94.46 34.68,92.37 v1(35.1,91.95)
  BOTTOM w0.102: v1(34.3,95.1) 34.52,95.32 34.52,96.23 34.7,96.41 34.7,104.5 35,104.8 35,107.2 34.7,107.5 U12.M2 v1(34.3,108.9)
DDR_A11: length 38.7
  TOP w0.102: v1(32.7,91.15) 32.7,91.1 U13.P7 ; U12.P7 v1(32.7,104.1) ; U2.P1 v1(51.25,90.15)
  INNER2 w0.102: v1(32.7,91.15) 32.7,93.76 32.32,94.14 32.32,95.27 32.94,95.89 32.94,101.68 32.32,102.3 32.32,103.46 32.7,103.84 v1(32.7,104.1)
  BOTTOM w0.102: v1(51.25,90.15) 51.25,89.69 50.87,89.31 50.87,89.25 49.45,87.84 35.61,87.84 35.13,88.32 33.33,88.32 33.1,88.55 33.1,88.9 32.88,89.12 32.54,89.12 32.32,89.34 32.32,89.66 32.7,90.04 v1(32.7,91.15)
DDR_A12: length 43
  TOP w0.102: U13.R2 v1(31.9,95.1) ; U2.R1 v1(51.25,89.15) ; U12.R2 v1(31.9,108.9)
  INNER2 w0.1: v1(31.9,95.1) 31.9,95.15 32.75,96 32.75,101.61 32.14,102.22 32.14,108.66 v1(31.9,108.9)
  BOTTOM w0.102: v1(31.9,95.1) 32.1,94.9 32.1,88.76 32.72,88.14 35.05,88.14 35.54,87.65 49.53,87.65 51.02,89.15 v1(51.25,89.15)
DDR_BA0: length 34.6
  TOP w0.102: U13.L1 v1(35.1,95.9) ; U2.M2 v1(52.25,92.15) ; U12.L2 v1(35.1,108.9)
  INNER2 w0.1: 51.4,92.53 51.41,92.53 51.79,92.15 v1(52.25,92.15)
  INNER2 w0.102: 51.4,92.53 51.09,92.53 51.03,92.47 45.73,92.47 v1(45.15,93.05)
  BOTTOM w0.102: v1(45.15,93.05) 44.65,93.55 39.95,93.55 38.8,94.7 36.3,94.7 v1(35.1,95.9) 35.1,100.45 36.28,101.63 36.28,107.07 35.5,107.85 U12.L2 v1(35.1,108.9)
DDR_BA1: length 41.1
  TOP w0.102: U2.P2 v1(52.25,90.15) ; U12.L3 v1(35.1,108.1) ; U13.L3 v1(35.1,94.3)
  INNER1 w0.102: v1(35.1,94.3) 34.68,94.72 34.68,107.68 v1(35.1,108.1)
  BOTTOM w0.102: v1(52.25,90.15) 52.25,90.6 51.85,91 51.85,91.3 51.62,91.53 50.58,91.53 50.32,91.27 50.32,89.53 49.91,89.12 48.79,89.12 48.75,89.16 48.05,89.16 48.01,89.12 47.79,89.12 47.75,89.16 47.05,89.16 47.01,89.12 35.62,89.12 35.5,89.24 35.5,92.1 35.1,92.5 v1(35.1,94.3)
DDR_BA2: length 58.7
  TOP w0.102: U13.L2 v1(35.1,95.1) ; U2.R2 v1(52.25,89.15) ; U12.L1 v1(35.1,109.7)
  INNER2 w0.102: v1(35.1,109.7) 34.68,109.28 31.73,109.28 31.52,109.07 31.52,108.74 31.96,108.3 31.96,102.15 32.57,101.54 32.57,96.08 32.04,95.55 31.8,95.55 31.35,95.1 31.25,95.1 31.25,91.92 32.42,90.75 34.1,90.75 34.7,91.35 34.7,94.7 v1(35.1,95.1)
  BOTTOM w0.102: v1(52.25,89.15) 52.15,89.15 51.63,89.67 51.63,90.31 51.41,90.53 51.09,90.53 50.69,90.13 50.69,89.33 49.38,88.02 35.72,88.02 34.72,89.02 34.72,94.72 v1(35.1,95.1)
DDR_CAS: length 37.4
  TOP w0.1: v1(35.9,91.1) 36.25,91.45 44.1,91.45 46.27,89.28 46.27,88.54 47.06,87.75 52.85,87.75 U2.T3
  TOP w0.102: U12.L7 v1(35.1,104.1) ; U13.L7 v1(35.9,91.1)
  INNER2 w0.102: v1(35.9,91.1) 36.1,91.3 36.1,93.4 36.28,93.58 36.28,96.27 36.05,96.5 34.45,96.5 33.9,97.05 33.9,101.25 35.18,102.53 35.18,102.68 35.5,103 35.5,103.7 v1(35.1,104.1)
DDR_CK_N: length 40.6
  TOP w0.102: U2.T5 v1(55.25,88.15) ; U13.J8 v1(36.7,89.5) ; U12.J8 v1(36.7,103.3)
  INNER1 w0.102: v1(36.7,89.5) 37.1,89.1 37.1,88 38.2,86.9 54,86.9 v1(55.25,88.15)
  INNER2 w0.1: 37.3,93.9 36.48,93.08 36.48,90.88 36.32,90.71 36.32,89.88 v1(36.7,89.5) ; v1(36.7,103.3) 36.7,103.2 36.3,102.8 36.3,102.25 36.15,102.1 35.35,102.1 34.3,101.05 34.3,97.25 34.65,96.9 36.25,96.9 36.64,96.51 36.64,96.46 36.65,96.45
  INNER2 w0.102: 37.3,93.9 37.3,94.6 36.65,95.25 36.65,96.45
DDR_CK_P: length 41.1
  TOP w0.102: U12.K8 v1(35.9,103.3) ; U13.K8 v1(35.9,89.5) ; U2.R5 v1(55.25,89.15)
  INNER1 w0.102: v1(55.25,89.15) 55.7,88.7 55.7,87.5 54.9,86.7 37.55,86.7 36.3,87.95 36.3,89.1 v1(35.9,89.5)
  BOTTOM w0.102: v1(35.9,103.3) 35.52,102.92 35.52,102.34 35.7,102.16 35.7,101.35 34.9,100.55 34.9,96.35 34.7,96.15 34.7,95.65 34.85,95.5 35.24,95.5 35.48,95.26 35.48,95.22 35.5,95.2 35.5,92.55 36.28,91.77 36.28,89.88 v1(35.9,89.5)
DDR_CKE: length 43.4
  TOP w0.102: U12.K2 v1(35.9,108.9) ; U13.K2 35.9,95.1 v1(35.9,95.9) ; U2.T4 v1(54.25,88.15)
  INNER1 w0.102: v1(54.25,88.15) 53.2,87.1 38.3,87.1 37.3,88.1 37.3,90.35 36.3,91.35 U13.K2 35.9,95.1 v1(35.9,95.9)
  BOTTOM w0.1: 35.9,95.95 35.28,96.57 35.28,100.38 36.46,101.56 36.46,101.56 37.15,102.25
  BOTTOM w0.102: v1(35.9,108.9) U12.K2 36.3,107.85 37.15,107 37.15,102.25 ; 35.9,95.95 v1(35.9,95.9)
DDR_CS1: length 38.1
  TOP w0.102: U2.P5 v1(55.25,90.15) ; U12.L8 v1(35.1,103.3)
  INNER1 w0.102: v1(55.25,90.15) 55.25,90.14 54.7,89.59 54,89.59 51.7,87.28 38.38,87.28 37.48,88.18 37.48,90.77 37.08,91.17 37.08,94.52 36.85,94.75 36.85,96.96 37.48,97.59 37.48,100.67 37.15,101 37.15,102.65 36.88,102.92 35.48,102.92 v1(35.1,103.3)
DDR_CS2: length 25.2
  TOP w0.102: U2.N5 v1(55.25,91.15) ; U13.L8 v1(35.1,89.5)
  BOTTOM w0.102: v1(35.1,89.5) 35.1,88.9 35.8,88.2 49.25,88.2 50.5,89.45 50.5,90.2 51.02,90.71 51.48,90.71 51.81,90.38 51.81,89.94 52.05,89.7 54.05,89.7 54.7,90.35 54.7,90.6 v1(55.25,91.15)
DDR_DQ0: length 20.1
  TOP w0.102: U2.F5 v1(55.25,99.15) ; U12.G8 v1(39.1,103.3)
  INNER1 w0.102: v1(55.25,99.15) 54.63,98.53 50.42,98.53 49.95,99 49.55,99 49.38,99.16 48.92,99.16 48.75,99 47.05,99 46.88,99.16 46.42,99.16 46.25,99 43.66,99 40.3,102.36 40.3,102.65 40.05,102.9 39.5,102.9 v1(39.1,103.3)
DDR_DQ1: length 19.8
  TOP w0.102: U12.G2 v1(39.1,108.9) ; U2.C2 v1(52.25,102.15)
  INNER1 w0.102: v1(39.1,108.9) 39.1,108.4 39.01,108.31 38.95,108.31 38.86,108.22 38.86,108.1 38.95,108.01 39.01,108.01 39.1,107.92 39.1,107.8 39.01,107.71 38.95,107.71 38.86,107.62 38.86,107.49 38.95,107.41 39.01,107.41 39.1,107.32 39.1,107.19 39.01,107.1 38.95,107.1 38.86,107.02 38.86,106.89 38.95,106.8 39.01,106.8 39.1,106.71 39.1,106.4 40.63,104.86 48.45,104.86 49.91,103.4 49.91,102.84 50.22,102.53 51.87,102.53 v1(52.25,102.15)
DDR_DQ2: length 21.6
  TOP w0.102: U2.F4 v1(54.25,99.15) ; U12.H7 v1(38.3,104.1)
  INNER1 w0.102: v1(54.25,99.15) 53.81,98.71 50.58,98.71 49.31,99.98 48.99,99.98 48.28,99.27 47.52,99.27 46.81,99.98 46.49,99.98 45.71,99.2 43.72,99.2 41.1,101.82 41.1,103 40.38,103.72 38.68,103.72 v1(38.3,104.1)
DDR_DQ3: length 22.3
  TOP w0.102: U2.E4 v1(54.25,100.15) ; U12.H3 v1(38.3,108.1)
  INNER1 w0.102: v1(38.3,108.1) 38.3,106.4 40.2,104.5 48.3,104.5 49.55,103.25 49.55,102.1 50.12,101.53 52.41,101.53 52.85,101.09 52.85,100.95 53.15,100.65 53.75,100.65 v1(54.25,100.15)
DDR_DQ4: length 22.1
  TOP w0.102: U2.D3 v1(53.25,101.15) ; U12.H1 v1(38.3,109.7)
  INNER1 w0.102: v1(53.25,101.15) 52.69,101.71 50.29,101.71 49.73,102.28 49.73,103.33 48.38,104.68 40.42,104.68 38.68,106.42 38.68,109.32 v1(38.3,109.7)
DDR_DQ5: length 20.8
  TOP w0.102: U12.H9 v1(38.3,102.5) ; U2.G5 v1(55.25,98.15)
  INNER1 w0.102: v1(55.25,98.15) 54.63,97.53 50.62,97.53 50.15,98 49.55,98 49.38,98.16 48.92,98.16 48.75,98 47.05,98 46.88,98.16 46.42,98.16 46.25,98 44,98 40.06,101.94 38.86,101.94 v1(38.3,102.5)
DDR_DQ6: length 20.3
  TOP w0.102: U12.F1 v1(39.9,109.7) ; U2.C3 v1(53.25,102.15)
  INNER1 w0.102: v1(53.25,102.15) 52.67,102.73 50.84,102.73 48.53,105.05 40.85,105.05 39.48,106.42 39.48,109.28 v1(39.9,109.7)
DDR_DQ7: length 20.1
  TOP w0.102: U2.G3 v1(53.25,98.15) ; U12.F9 v1(39.9,102.5)
  INNER1 w0.102: v1(53.25,98.15) 52.81,97.71 50.7,97.71 50.23,98.18 50.11,98.18 49.31,98.98 48.99,98.98 48.28,98.27 47.52,98.27 46.81,98.98 46.49,98.98 45.69,98.18 45.55,98.18 45.46,98.27 45.46,98.73 45.37,98.82 45.23,98.82 45.14,98.73 45.14,98.28 45.04,98.18 44.89,98.18 44.79,98.28 44.79,98.7 44.69,98.8 44.54,98.8 44.44,98.7 44.44,98.3 44.34,98.2 44.1,98.2 39.9,102.4 v1(39.9,102.5)
DDR_DQ8: length 19.9
  TOP w0.102: U12.C8 v1(42.3,103.3) ; U2.E2 v1(52.25,100.15)
  INNER1 w0.102: v1(52.25,100.15) 51.87,100.53 50.18,100.53 50.08,100.63 50.08,100.73 49.97,100.84 49.77,100.84 49.67,100.73 49.67,100.63 49.57,100.53 49.36,100.53 49.26,100.63 49.26,101.2 49.16,101.3 48.95,101.3 48.85,101.2 48.85,100.63 48.75,100.53 48.55,100.53 48.44,100.63 48.44,101.2 48.34,101.3 48.14,101.3 48.04,101.2 48.04,100.63 47.93,100.53 47.73,100.53 47.63,100.63 47.63,100.85 47.53,100.95 47.27,100.95 47.18,101.04 47.18,101.26 47.09,101.35 46.97,101.35 46.88,101.26 46.88,101.04 46.79,100.95 46.66,100.95 46.58,101.04 46.58,101.26 46.49,101.35 46.36,101.35 46.27,101.26 46.27,101.04 46.19,100.95 46.06,100.95 45.97,101.04 45.97,101.26 45.88,101.35 45.76,101.35 45.67,101.26 45.67,101.04 45.58,100.95 45.28,100.95 45.02,101.21 44.87,101.21 44.77,101.11 44.77,100.94 44.67,100.84 44.06,100.84 43.96,100.73 43.96,100.63 43.85,100.53 43.19,100.53 42.7,101.02 42.7,101.52 42.6,101.62 42.33,101.62 42.23,101.72 42.23,101.93 42.33,102.03 42.6,102.03 42.7,102.13 42.7,102.9 v1(42.3,103.3)
DDR_DQ9: length 20
  TOP w0.102: U2.B3 v1(53.25,103.15) ; U12.C2 v1(42.3,108.9)
  INNER1 w0.102: v1(53.25,103.15) 52.65,103.75 50.6,103.75 48.76,105.59 43.61,105.59 43.36,105.84 43.36,105.98 43.6,106.22 43.73,106.22 44.14,105.81 44.26,105.81 44.35,105.9 44.35,106.03 43.94,106.44 43.94,106.56 44.32,106.94 44.32,107.08 44.17,107.23 44.03,107.23 43.32,106.52 43.18,106.52 43.08,106.62 43.08,106.81 43.18,106.92 43.25,106.92 43.35,107.02 43.35,107.55 43.25,107.65 42.78,107.65 42.68,107.75 42.68,108.52 v1(42.3,108.9)
DDR_DQ10: length 19.7
  TOP w0.102: U12.D7 v1(41.5,104.1) ; U2.F3 v1(53.25,99.15)
  INNER1 w0.102: v1(41.5,104.1) 41.5,103.84 41.88,103.46 41.88,101.55 43.09,100.34 45.15,100.34 45.24,100.43 45.24,100.66 45.33,100.75 45.45,100.75 45.54,100.66 45.54,100.43 45.63,100.34 45.76,100.34 45.84,100.43 45.84,100.66 45.93,100.75 46.06,100.75 46.15,100.66 46.15,100.43 46.23,100.34 46.36,100.34 46.45,100.43 46.45,100.66 46.54,100.75 46.66,100.75 46.75,100.66 46.75,100.43 46.84,100.34 46.97,100.34 47.05,100.43 47.05,100.66 47.14,100.75 47.27,100.75 47.35,100.66 47.35,100.43 47.44,100.34 49.46,100.34 50.09,99.71 50.3,99.71 50.4,99.81 50.4,100.22 50.5,100.33 50.7,100.33 50.81,100.22 50.81,99.81 50.91,99.71 52.69,99.71 v1(53.25,99.15)
DDR_DQ11: length 19.9
  TOP w0.102: U12.D3 v1(41.5,108.1) ; U2.B1 v1(51.25,103.15)
  INNER1 w0.102: v1(51.25,103.15) 50.68,103.15 48.6,105.23 42.45,105.23 42.08,105.6 41.94,105.6 41.66,105.33 41.17,105.33 41.03,105.47 41.03,105.61 41.5,106.09 41.5,106.76 41.4,106.86 40.58,106.86 40.49,106.77 40.49,106.34 40.41,106.25 40.28,106.25 40.19,106.34 40.19,106.77 40.1,106.86 39.8,106.86 39.7,106.96 39.7,107.16 39.8,107.27 41.4,107.27 41.5,107.37 v1(41.5,108.1)
DDR_DQ12: length 19.8
  TOP w0.102: U12.D1 v1(41.5,109.7) ; U2.B2 v1(52.25,103.15)
  INNER1 w0.102: v1(41.5,109.7) 41.88,109.32 41.88,107.5 41.98,107.4 42.8,107.4 42.9,107.3 42.9,106.97 42.8,106.87 41.98,106.87 41.71,106.59 41.71,106.44 42.09,106.06 42.24,106.06 42.72,106.54 42.86,106.54 43.01,106.39 43.01,106.25 42.6,105.84 42.6,105.7 42.65,105.65 43.2,105.65 43.44,105.41 48.68,105.41 50.54,103.55 51.85,103.55 v1(52.25,103.15)
DDR_DQ13: length 20.4
  TOP w0.102: U2.F2 v1(52.25,99.15) ; U12.D9 v1(41.5,102.5)
  INNER1 w0.102: v1(52.25,99.15) 51.87,99.53 51.72,99.53 51.64,99.44 51.64,98.98 51.55,98.9 51.4,98.9 51.31,98.98 51.31,99.44 51.23,99.53 51.07,99.53 50.97,99.43 50.97,99 50.87,98.9 50.7,98.9 50.6,99 50.6,99.43 50.5,99.53 50.02,99.53 49.38,100.16 48.92,100.16 48.75,100 48.28,100 48.18,99.9 48.18,99.6 48.08,99.49 47.87,99.49 47.77,99.6 47.77,99.9 47.67,100 47.05,100 46.88,100.16 46.42,100.16 46.25,100 45.9,100 45.8,99.9 45.8,99.55 45.7,99.45 45.49,99.45 45.39,99.55 45.39,100.05 45.29,100.15 45.08,100.15 44.98,100.05 44.98,99.49 44.88,99.39 44.67,99.39 44.57,99.49 44.57,100.05 44.47,100.15 44.27,100.15 44.16,100.05 44.16,99.5 44.06,99.4 43.86,99.4 43.76,99.5 43.76,99.9 43.66,100 43.17,100 41.5,101.67 v1(41.5,102.5)
DDR_DQ14: length 19.8
  TOP w0.102: U12.B1 v1(43.1,109.7) ; U2.A2 v1(52.25,104.15)
  INNER1 w0.102: v1(52.25,104.15) 51.85,104.55 51.28,104.55 51.18,104.65 51.18,104.75 51.08,104.86 50.87,104.86 50.77,104.75 50.77,104.65 50.67,104.55 50.1,104.55 49.7,104.95 49.7,105.09 50.16,105.55 50.16,105.69 50.01,105.84 49.87,105.84 49.41,105.38 49.27,105.38 48.88,105.77 48.61,105.77 48.51,105.88 48.51,105.98 48.41,106.08 48.21,106.08 48.1,105.98 48.1,105.88 48,105.77 47.8,105.77 47.7,105.88 47.7,105.98 47.59,106.08 47.39,106.08 47.29,105.98 47.29,105.88 47.19,105.77 46.98,105.77 46.88,105.88 46.88,105.98 46.78,106.08 46.57,106.08 46.47,105.98 46.47,105.88 46.37,105.77 45.7,105.77 45.6,105.88 45.6,106.04 45.72,106.16 45.72,106.28 45.63,106.37 45.5,106.37 44.93,105.8 44.8,105.8 44.72,105.89 44.72,106.01 45.29,106.59 45.29,106.71 45.2,106.8 45.08,106.8 44.84,106.56 44.72,106.56 44.5,106.78 44.5,107.46 44.4,107.56 43.64,107.56 43.52,107.68 43.52,108.45 43.62,108.56 43.72,108.56 43.83,108.66 43.83,108.86 43.72,108.96 43.62,108.96 43.52,109.06 43.52,109.28 v1(43.1,109.7)
DDR_DQ15: length 19.8
  TOP w0.102: v1(53.25,100.15) U2.E3 ; U12.B9 v1(43.1,102.5)
  INNER1 w0.102: v1(43.1,102.5) 43.1,101.53 43.61,101.02 44.31,101.02 44.41,101.12 44.41,102.5 44.51,102.6 44.72,102.6 44.82,102.5 44.82,101.6 44.92,101.5 45.13,101.5 45.23,101.6 45.23,102.5 45.33,102.6 45.53,102.6 45.64,102.5 45.64,101.63 45.74,101.53 47.57,101.53 47.68,101.63 47.68,102.6 47.78,102.7 47.98,102.7 48.08,102.6 48.08,101.63 48.19,101.53 49.7,101.53 49.8,101.43 49.8,101.12 49.9,101.02 50.29,101.02 50.59,100.71 52.69,100.71 v1(53.25,100.15)
DDR_DQ16: length 19.8
  TOP w0.102: U13.G8 v1(39.1,89.5) ; U2.L3 v1(53.25,93.15)
  INNER1 w0.102: v1(53.25,93.15) 52.87,93.53 51.09,93.53 50.81,93.25 49,93.25 48.72,92.97 47.83,92.97 47.75,92.9 47.75,92.75 47.8,92.7 48.3,92.7 48.38,92.62 48.16,92.41 47.55,92.41 47.47,92.5 47.47,92.96 47.38,93.05 47.25,93.05 47.16,92.96 47.16,92.5 47.08,92.41 46.42,92.41 46.1,92.1 43.82,92.1 43.51,91.8 43.28,91.8 42.53,91.05 41.71,91.05 41.12,90.46 41.12,90.17 40.83,89.88 39.48,89.88 v1(39.1,89.5)
DDR_DQ17: length 19.9
  TOP w0.102: U13.G2 v1(39.1,95.1) ; U2.H5 v1(55.25,97.15)
  INNER1 w0.102: v1(55.25,97.15) 54.61,96.51 53.01,96.51 52.7,96.2 50.74,96.2 50.67,96.27 49.96,96.27 49.77,96.08 48.81,96.08 48.31,96.58 47.54,96.58 47.04,96.08 46.08,96.08 45.49,96.68 44.68,96.68 44.55,96.55 44.38,96.55 44.25,96.68 44.08,96.68 43.95,96.55 43.77,96.55 43.65,96.68 43.34,96.68 42.72,96.06 42.72,95.77 42.43,95.48 41.34,95.48 40.96,95.1 40.44,95.1 40.06,94.72 39.74,94.72 39.36,95.1 v1(39.1,95.1)
DDR_DQ18: length 19.8
  TOP w0.102: U2.K5 v1(55.25,94.15) ; U13.H7 v1(38.3,90.3)
  INNER1 w0.102: v1(55.25,94.15) 54.87,93.77 50.97,93.77 50.67,93.47 48.92,93.47 48.68,93.23 46.49,93.23 45.55,92.28 43.74,92.28 43.44,91.98 43.21,91.98 42.46,91.23 41.63,91.23 41.08,90.68 38.68,90.68 v1(38.3,90.3)
DDR_DQ19: length 19.7
  TOP w0.102: U2.K2 v1(52.25,94.15) ; U13.H3 v1(38.3,94.3)
  INNER1 w0.102: v1(38.3,94.3) 38.68,93.92 41.18,93.92 41.65,93.45 41.95,93.45 42.04,93.36 42.04,93.09 42.13,93 42.25,93 42.34,93.09 42.34,93.36 42.43,93.45 42.56,93.45 42.64,93.36 42.64,93.09 42.73,93 42.86,93 42.95,93.09 42.95,93.36 43.03,93.45 46,93.45 46.1,93.55 46.1,94.22 46.2,94.32 46.95,94.32 47.05,94.22 47.05,93.6 47.15,93.5 48.65,93.5 48.75,93.6 48.75,94.22 48.85,94.32 49.9,94.32 50,94.22 50,94.11 50.1,94.01 50.31,94.01 50.41,94.11 50.41,94.22 50.51,94.32 50.88,94.32 51.09,94.53 51.87,94.53 v1(52.25,94.15)
DDR_DQ20: length 20.4
  TOP w0.102: U13.H1 v1(38.3,95.9) ; U2.H3 v1(53.25,97.15)
  INNER1 w0.1: 39.65,95.52 39.5,95.67 39.5,96.95 39.35,97.1 38.5,97.1 38.3,96.9 v1(38.3,95.9)
  INNER1 w0.102: v1(53.25,97.15) 52.97,96.87 52.77,96.87 52.47,96.56 50.96,96.56 50.89,96.63 50.52,96.63 50.13,97.02 49.53,97.02 49.38,97.16 48.71,97.16 48.63,97.25 47.51,97.25 47.43,97.16 46.35,97.16 46.04,97.47 42.81,97.47 42.58,97.24 41.5,97.24 40.32,96.06 40.32,95.77 40.07,95.52 39.65,95.52
DDR_DQ21: length 20.2
  TOP w0.102: U2.L5 v1(55.25,93.15) ; U13.H9 v1(38.3,88.7)
  INNER1 w0.102: v1(55.25,93.15) 54.65,92.55 51.1,92.55 50.8,92.25 48.64,92.25 47.82,91.43 43.44,91.43 42.68,90.68 42.14,90.68 41.92,90.46 41.92,90.17 41.63,89.88 41.08,89.88 40.28,89.08 38.68,89.08 v1(38.3,88.7)
DDR_DQ22: length 19.8
  TOP w0.102: U13.F1 v1(39.9,95.9) ; U2.H2 52.35,97.05 v1(52.35,97.1)
  INNER1 w0.102: v1(39.9,95.9) 40.49,96.49 40.49,96.63 40.08,97.04 40.08,97.18 40.23,97.33 40.37,97.33 40.78,96.92 40.92,96.92 41.42,97.42 41.68,97.42 41.79,97.52 41.79,98.1 41.89,98.2 42.09,98.2 42.19,98.1 42.19,97.52 42.3,97.42 42.5,97.42 42.73,97.65 42.93,97.65 43.03,97.75 43.03,98.25 43.14,98.35 43.34,98.35 43.44,98.25 43.44,97.75 43.54,97.65 46.16,97.65 46.49,97.98 46.81,97.98 47.36,97.43 47.59,97.43 47.7,97.53 47.7,97.63 47.8,97.73 48,97.73 48.1,97.63 48.1,97.53 48.2,97.43 48.44,97.43 48.99,97.98 49.31,97.98 50.09,97.2 50.21,97.2 50.59,96.82 50.97,96.82 51.03,96.75 52,96.75 v1(52.35,97.1)
DDR_DQ23: length 19.9
  TOP w0.102: U2.M4 v1(54.25,92.15) ; U13.F9 v1(39.9,88.7)
  INNER1 w0.102: v1(39.9,88.7) 40.16,88.7 40.58,89.12 41.66,89.12 41.92,89.38 41.92,89.66 42.18,89.92 42.46,89.92 42.72,90.18 42.72,90.46 43.51,91.25 43.81,91.25 43.9,91.16 43.9,90.99 43.99,90.9 44.11,90.9 44.2,90.99 44.2,91.16 44.29,91.25 47.9,91.25 48.12,91.47 49.69,91.47 49.78,91.56 49.78,91.96 49.87,92.05 49.99,92.05 50.08,91.96 50.08,91.56 50.17,91.47 50.77,91.47 51.02,91.71 52.64,91.71 52.72,91.8 52.72,92.26 52.81,92.35 52.94,92.35 53.03,92.26 53.03,91.8 53.11,91.71 53.81,91.71 v1(54.25,92.15)
DDR_DQ24: length 19.8
  TOP w0.102: U2.M5 v1(55.25,92.15) ; U13.C8 v1(42.3,89.5)
  INNER1 w0.102: v1(55.25,92.15) 54.63,91.53 51.87,91.53 51.78,91.44 51.78,91.29 51.7,91.2 51.49,91.2 51.4,91.29 51.4,91.44 51.31,91.53 51.09,91.53 50.79,91.23 50.39,91.23 50.29,91.13 50.29,90.75 50.19,90.65 49.98,90.65 49.88,90.75 49.88,91.13 49.78,91.23 48.73,91.23 47.9,90.4 47.59,90.4 47.5,90.49 47.5,90.91 47.42,91 47.29,91 47.2,90.91 47.2,90.49 47.11,90.4 46.02,90.4 45.91,90.5 45.91,90.85 45.81,90.95 45.61,90.95 45.5,90.85 45.5,90.5 45.4,90.4 45.2,90.4 45.1,90.5 45.1,90.85 44.99,90.95 44.79,90.95 44.69,90.85 44.69,90.5 44.59,90.4 44.34,90.4 44.06,90.68 43.74,90.68 43.52,90.46 43.52,90.17 43.23,89.88 42.68,89.88 v1(42.3,89.5)
DDR_DQ25: length 19.9
  TOP w0.102: U13.C2 v1(42.3,95.1) ; U2.J3 v1(53.25,95.15)
  INNER1 w0.102: v1(53.25,95.15) 52.87,95.53 52.28,95.53 52.18,95.63 52.18,95.73 52.08,95.84 51.88,95.84 51.77,95.73 51.77,95.63 51.64,95.5 51.35,95.5 51.25,95.4 51.25,95 51.15,94.9 50.85,94.9 50.7,94.75 50.55,94.75 50.42,94.88 50.42,95.03 50.26,95.19 50.26,95.5 50.16,95.6 50.01,95.6 49.91,95.5 49.91,95.19 49.81,95.09 48.64,95.09 48.53,95.19 48.53,95.5 48.43,95.6 48.29,95.6 48.19,95.5 48.19,94.95 48.08,94.85 47.82,94.85 47.72,94.95 47.72,95.5 47.62,95.6 47.41,95.6 47.31,95.5 47.31,95.19 47.21,95.09 46.24,95.09 46.15,95 46.15,94.79 46.06,94.7 45.94,94.7 45.85,94.79 45.85,95 45.76,95.09 45.64,95.09 45.55,95 45.55,94.79 45.46,94.7 45.33,94.7 45.25,94.79 45.25,95 45.16,95.09 45.03,95.09 44.95,95 44.95,94.34 44.86,94.25 44.73,94.25 44.64,94.34 44.64,95 44.55,95.09 44.43,95.09 44.34,95 44.34,94.79 44.25,94.7 44.13,94.7 44.04,94.79 44.04,95 43.95,95.09 43.65,95.09 43.26,95.48 42.94,95.48 42.56,95.1 v1(42.3,95.1)
